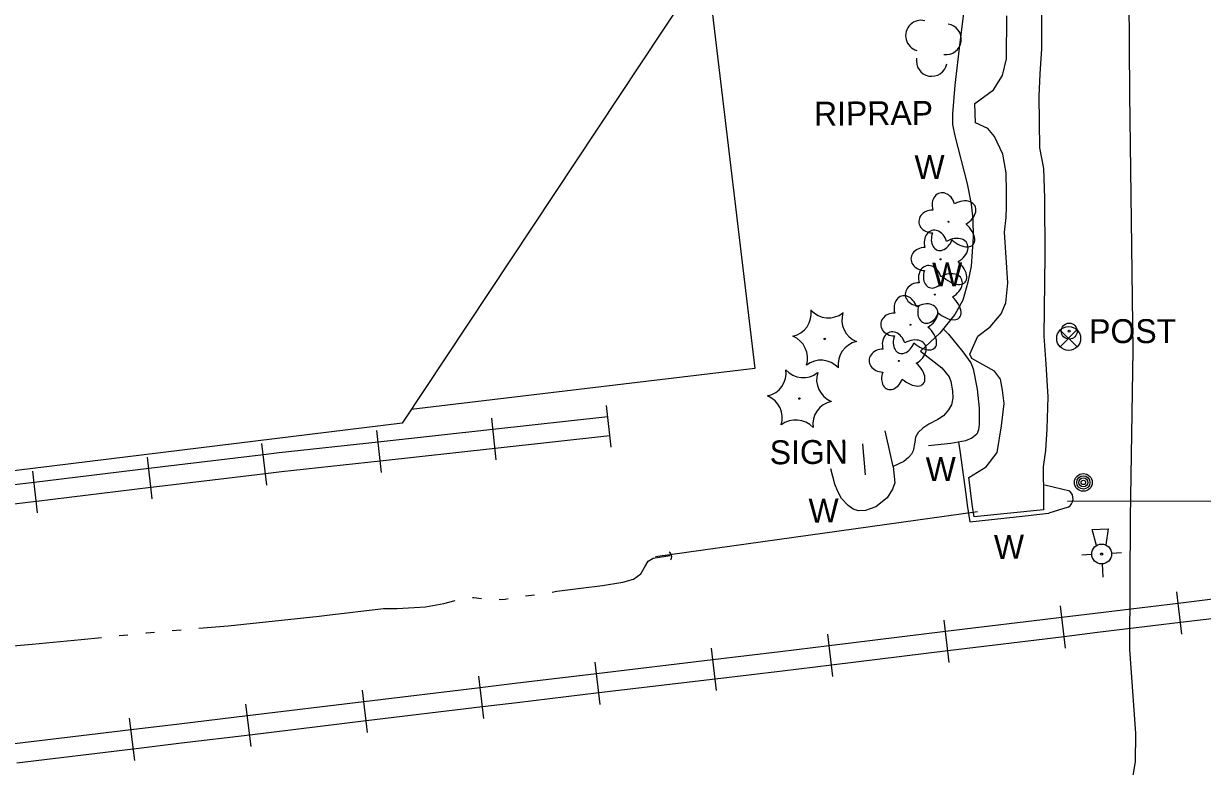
# Model space of a CAD drawing. Extents: x 589250 to 1188077, y 162953 to 363065.
# Drawn here: x 592485.5 to 592781.4, y 174759.1 to 174945.5 of the extents above; entities that cross this region are included whole.
import ezdxf

# ---------------------------------------------------------------- set-up
doc = ezdxf.new("R2010")
doc.units = 0
for name, color, linetype in [('E_BLD', 7, 'Continuous'), ('E_DRN', 7, 'Continuous'), ('E_DRN_Pipe', 7, 'Continuous'), ('E_DRN_RipRap', 7, 'Continuous'), ('E_DRN_RipRap_Text', 7, 'Continuous'), ('E_LAND_TreeLine_P', 7, 'Continuous'), ('E_LAND_Vegetation', 7, 'Continuous'), ('E_MAP_Limits', 7, 'Continuous'), ('E_MISCPROP', 7, 'Continuous'), ('E_RDWY', 7, 'Continuous'), ('E_RR_P', 7, 'Continuous'), ('E_RR_Utility', 7, 'Continuous'), ('E_SGN', 7, 'Continuous'), ('E_SGN_Text', 7, 'Continuous'), ('E_SIG', 7, 'Continuous'), ('E_STRUCT', 7, 'Continuous'), ('E_WAL', 7, 'Continuous'), ('E_WAL_Text', 7, 'Continuous'), ('E_WTR_FlowLine', 7, 'Continuous')]:
    doc.layers.add(name, color=color, linetype=linetype)

msp = doc.modelspace()

# ---------------------------------------------------------------- linework, layer by layer
at = {"layer": 'E_BLD'}
for p, q in [((592638.46, 175115.52), (592669, 174858.96)), ((592669, 174858.96), (592582.79, 174848.7))]:
    msp.add_line(p, q, dxfattribs=at)
at = {"layer": 'E_DRN'}
for centre, radius, start, end in [((592746.36, 174826.32), 2.56, 302.1619, 48.4222), ((592646.97, 174811.79), 1.21, 315.4865, 61.7467)]:
    msp.add_arc(centre, radius, start, end, dxfattribs=at)
at = {"layer": 'E_DRN_Pipe'}
for p, q in [((592747.53, 174825.68), (592807.85, 174825.81)), ((592724.94, 174823.05), (592644.14, 174811.7))]:
    msp.add_line(p, q, dxfattribs=at)
at = {"layer": 'E_DRN_RipRap'}
for p, q in [((592740.99, 174954.39), (592740.97, 174939.17)), ((592732.21, 174936.63), (592732.27, 174947.45)), ((592740.97, 174939.17), (592740.58, 174932.88)), ((592731.22, 174932.52), (592732.21, 174936.63)), ((592728.92, 174928.85), (592731.22, 174932.52)), ((592740.58, 174932.88), (592740.34, 174927.32)), ((592724.26, 174925.44), (592728.92, 174928.85)), ((592740.34, 174927.32), (592740.45, 174914.3)), ((592724.45, 174920.62), (592724.26, 174925.44)), ((592727.53, 174919.18), (592724.45, 174920.62)), ((592729.16, 174917.14), (592727.53, 174919.18)), ((592731.25, 174912.77), (592729.16, 174917.14)), ((592732.16, 174908.1), (592731.25, 174912.77)), ((592740.45, 174914.3), (592741.52, 174909.19)), ((592732.2, 174903.42), (592732.16, 174908.1)), ((592741.52, 174909.19), (592741.73, 174901.73)), ((592732.24, 174899.47), (592732.2, 174903.42)), ((592741.73, 174901.73), (592741.85, 174887.41)), ((592732.11, 174896.84), (592732.24, 174899.47)), ((592731.7, 174893.18), (592732.11, 174896.84)), ((592732.54, 174880.46), (592731.7, 174893.18)), ((592741.85, 174887.41), (592741.58, 174867.07)), ((592732, 174875.48), (592732.54, 174880.46)), ((592730.85, 174872.69), (592732, 174875.48)), ((592728.1, 174869.45), (592730.85, 174872.69)), ((592725.05, 174867.08), (592728.1, 174869.45)), ((592723.04, 174862.53), (592725.05, 174867.08)), ((592741.58, 174867.07), (592742.08, 174860.06)), ((592723.49, 174861.51), (592723.04, 174862.53)), ((592729.22, 174858.34), (592723.49, 174861.51)), ((592742.08, 174860.06), (592742.59, 174851.87)), ((592730.7, 174856.3), (592729.22, 174858.34)), ((592731.16, 174853.53), (592730.7, 174856.3)), ((592731.63, 174850.17), (592731.16, 174853.53)), ((592742.59, 174851.87), (592742.36, 174843.82)), ((592730.95, 174844.6), (592731.63, 174850.17)), ((592729.83, 174837.86), (592730.95, 174844.6)), ((592742.36, 174843.82), (592741.97, 174838.4)), ((592741.97, 174838.4), (592741.42, 174834.3)), ((592727.08, 174834.33), (592729.83, 174837.86)), ((592722.72, 174831.66), (592727.08, 174834.33)), ((592741.42, 174834.3), (592741.44, 174831.67)), ((592723.66, 174824.35), (592722.72, 174831.66)), ((592741.44, 174831.67), (592741.46, 174829.18)), ((592741.46, 174829.18), (592741.48, 174827.14)), ((592741.48, 174827.14), (592741.51, 174823.48)), ((592724.12, 174821.72), (592723.66, 174824.35)), ((592741.51, 174823.48), (592724.12, 174821.72))]:
    msp.add_line(p, q, dxfattribs=at)
at = {"layer": 'E_LAND_TreeLine_P'}
for centre, start, end in [((592710.73, 174942.48), 74.7778, 254.7778), ((592717, 174941.56), 262.1206, 82.1206), ((592713.43, 174936.13), 169.1765, 349.1765)]:
    msp.add_arc(centre, 3.85, start, end, dxfattribs=at)
at = {"layer": 'E_LAND_Vegetation'}
for centre, radius in [((592717.65, 174895.8), 0.128), ((592715.66, 174886.37), 0.128), ((592714.23, 174877.52), 0.128), ((592708.08, 174869.95), 0.128), ((592686.58, 174866.4), 0.167), ((592705.15, 174860.89), 0.128), ((592680.24, 174851.41), 0.167)]:
    msp.add_circle(centre, radius, dxfattribs=at)
for centre, radius, start, end in [((592677.32, 174872.84), 5.9, 282.2939, 8.0588), ((592687.5, 174877.57), 5.9, 222.2893, 308.0542), ((592696.78, 174871.19), 5.9, 162.2939, 248.0588), ((592676.37, 174861.6), 5.9, 342.2939, 68.0588), ((592695.83, 174859.96), 5.9, 102.2939, 188.0588), ((592685.63, 174855.15), 5.91, 42.3337, 128.0098), ((592670.98, 174857.85), 5.9, 282.2939, 8.0588), ((592681.17, 174862.59), 5.9, 222.2893, 308.0542), ((592690.44, 174856.2), 5.9, 162.2939, 248.0588), ((592670.04, 174846.61), 5.9, 342.2939, 68.0588), ((592689.5, 174844.97), 5.9, 102.2939, 188.0588), ((592679.29, 174840.16), 5.91, 42.3337, 128.0098)]:
    msp.add_arc(centre, radius, start, end, dxfattribs=at)
for centre, major_axis, ratio in [((592716.43, 174899.51), (0.99, -3.48), 0.782863), ((592720.59, 174897.74), (-3.67, -2.09), 0.691916), ((592713.66, 174895.86), (3.45, -0.05), 0.832022), ((592720.28, 174893.23), (-3.54, 3.17), 0.560249), ((592714.44, 174890.09), (0.99, -3.48), 0.782863), ((592716.07, 174892.11), (1.23, 3.41), 0.716896), ((592718.61, 174888.32), (-3.67, -2.09), 0.691916), ((592711.67, 174886.44), (3.45, -0.05), 0.832022), ((592718.29, 174883.81), (-3.54, 3.17), 0.560249), ((592713.01, 174881.23), (0.99, -3.48), 0.782863), ((592714.08, 174882.69), (1.23, 3.41), 0.716896), ((592717.18, 174879.47), (-3.67, -2.09), 0.691916), ((592710.24, 174877.59), (3.45, -0.05), 0.832022), ((592706.87, 174873.66), (0.99, -3.48), 0.782863), ((592716.86, 174874.95), (-3.54, 3.17), 0.560249), ((592712.65, 174873.84), (1.23, 3.41), 0.716896), ((592711.03, 174871.89), (-3.67, -2.09), 0.691916), ((592704.1, 174870.01), (3.45, -0.05), 0.832022), ((592703.93, 174864.61), (0.99, -3.48), 0.782863), ((592710.72, 174867.38), (-3.54, 3.17), 0.560249), ((592706.51, 174866.26), (1.23, 3.41), 0.716896), ((592708.1, 174862.84), (-3.67, -2.09), 0.691916), ((592701.17, 174860.96), (3.45, -0.05), 0.832022), ((592707.79, 174858.32), (-3.54, 3.17), 0.560249), ((592703.57, 174857.21), (1.23, 3.41), 0.716896)]:
    msp.add_ellipse(centre, major_axis=major_axis, ratio=ratio, start_param=1.570796, end_param=4.712389, dxfattribs=at)
at = {"layer": 'E_MAP_Limits'}
for p, q in [((592651.48, 174952.24), (592580.53, 174845.29)), ((592580.53, 174845.29), (592288.04, 174809.26))]:
    msp.add_line(p, q, dxfattribs=at)
at = {"layer": 'E_MISCPROP'}
for centre, radius in [((592747.95, 174868.35), 2), ((592747.95, 174868.35), 0.25), ((592751.49, 174830.39), 2.23), ((592751.49, 174830.39), 1.67), ((592751.49, 174830.39), 1.12), ((592751.49, 174830.39), 0.558)]:
    msp.add_circle(centre, radius, dxfattribs=at)
at = {"layer": 'E_RDWY'}
for p, q in [((592763.13, 174927.84), (592762.93, 174967.64)), ((592763.54, 174896.11), (592763.13, 174927.84)), ((592763.96, 174863.54), (592763.54, 174896.11)), ((592763.33, 174821.47), (592763.96, 174863.54)), ((592763.18, 174788.6), (592763.33, 174821.47)), ((592764.63, 174767.37), (592763.18, 174788.6)), ((592764.55, 174760.29), (592764.63, 174767.37)), ((592763.61, 174754.33), (592764.55, 174760.29))]:
    msp.add_line(p, q, dxfattribs=at)
at = {"layer": 'E_RR_P'}
for p, q in [((592632.96, 174839.22), (592631.82, 174849.68)), ((592604.14, 174836.07), (592603, 174846.53)), ((592632.13, 174846.83), (592603.32, 174843.68)), ((592575.33, 174832.91), (592574.19, 174843.38)), ((592603.31, 174843.68), (592574.5, 174840.53)), ((592632.65, 174842.07), (592603.84, 174838.92)), ((592546.6, 174829.73), (592545.34, 174840.17)), ((592574.5, 174840.53), (592549.68, 174837.81)), ((592603.83, 174838.92), (592575.02, 174835.76)), ((592517.82, 174826.25), (592516.57, 174836.69)), ((592545.69, 174837.33), (592516.91, 174833.85)), ((592549.68, 174837.81), (592545.69, 174837.33)), ((592575.02, 174835.76), (592550.23, 174833.05)), ((592489.04, 174822.77), (592487.79, 174833.22)), ((592516.91, 174833.85), (592488.13, 174830.37)), ((592546.26, 174832.57), (592517.49, 174829.09)), ((592550.23, 174833.05), (592546.26, 174832.57)), ((592488.13, 174830.37), (592466.38, 174827.74)), ((592517.48, 174829.09), (592488.71, 174825.61)), ((592488.7, 174825.61), (592466.96, 174822.99)), ((592776.22, 174792.33), (592774.94, 174802.94)), ((592804.49, 174803.59), (592775.29, 174800.05)), ((592775.29, 174800.05), (592754.46, 174797.52)), ((592747.02, 174788.79), (592745.74, 174799.39)), ((592754.46, 174797.52), (592746.09, 174796.5)), ((592805.07, 174798.76), (592775.88, 174795.22)), ((592717.83, 174785.24), (592716.54, 174795.84)), ((592746.09, 174796.5), (592716.9, 174792.96)), ((592775.87, 174795.22), (592755.05, 174792.7)), ((592688.63, 174781.69), (592687.35, 174792.3)), ((592716.89, 174792.96), (592687.7, 174789.41)), ((592746.68, 174791.68), (592717.48, 174788.13)), ((592755.05, 174792.7), (592746.68, 174791.68)), ((592659.41, 174778.17), (592658.15, 174788.78)), ((592687.69, 174789.41), (592675.36, 174787.91)), ((592717.48, 174788.13), (592688.28, 174784.58)), ((592630.21, 174774.68), (592628.94, 174785.28)), ((592658.49, 174785.89), (592629.29, 174782.39)), ((592675.36, 174787.91), (592658.49, 174785.89)), ((592629.29, 174782.39), (592608.77, 174779.94)), ((592675.95, 174783.08), (592659.07, 174781.06)), ((592688.28, 174784.58), (592675.95, 174783.08)), ((592601.01, 174771.17), (592599.74, 174781.78)), ((592608.77, 174779.94), (592600.09, 174778.89)), ((592659.07, 174781.06), (592629.87, 174777.57)), ((592571.81, 174767.65), (592570.53, 174778.25)), ((592600.08, 174778.89), (592570.88, 174775.36)), ((592629.86, 174777.57), (592609.35, 174775.11)), ((592542.61, 174764.12), (592541.33, 174774.73)), ((592570.88, 174775.36), (592541.68, 174771.84)), ((592600.66, 174774.06), (592571.47, 174770.54)), ((592609.35, 174775.11), (592600.67, 174774.06)), ((592513.4, 174760.61), (592512.13, 174771.21)), ((592541.68, 174771.84), (592524.56, 174769.77)), ((592571.46, 174770.54), (592542.27, 174767.01)), ((592512.48, 174768.32), (592483.27, 174764.83)), ((592524.56, 174769.77), (592512.48, 174768.32)), ((592525.14, 174764.95), (592513.06, 174763.5)), ((592542.26, 174767.01), (592525.14, 174764.95)), ((592513.05, 174763.5), (592483.85, 174760))]:
    msp.add_line(p, q, dxfattribs=at)
at = {"layer": 'E_RR_Utility'}
for p, q in [((592753.59, 174812.29), (592751.09, 174812.15)), ((592761.07, 174812.7), (592758.58, 174812.56)), ((592756.22, 174809.93), (592756.4, 174806.63))]:
    msp.add_line(p, q, dxfattribs=at)
msp.add_lwpolyline([(592754.81, 174814.58), (592753.74, 174818.56), (592757.74, 174818.78), (592757.11, 174814.7)], dxfattribs=at)
for radius in [2.5, 0.25]:
    msp.add_circle((592756.08, 174812.43), radius, dxfattribs=at)
at = {"layer": 'E_SGN'}
msp.add_line((592696.05, 174840.05), (592696.76, 174832.26), dxfattribs=at)
at = {"layer": 'E_SIG'}
for points in [[(592749.86, 174868.65), (592745.67, 174864.42)], [(592745.67, 174868.61), (592749.9, 174864.38)]]:
    msp.add_lwpolyline(points, dxfattribs=at)
msp.add_circle((592747.81, 174866.53), 3, dxfattribs=at)
at = {"layer": 'E_STRUCT'}
for p, q in [((592748.06, 174828.24), (592741.86, 174829.67)), ((592747.72, 174824.15), (592742.79, 174822.65))]:
    msp.add_line(p, q, dxfattribs=at)
at = {"layer": 'E_WAL'}
for p, q in [((592722.51, 174957.1), (592720.51, 174940.74)), ((592720.51, 174940.74), (592719.21, 174930.05)), ((592719.21, 174930.05), (592718.63, 174922.89)), ((592718.63, 174922.89), (592718.65, 174920.22)), ((592718.65, 174920.22), (592719.21, 174917.34)), ((592719.21, 174917.34), (592722.31, 174905.3)), ((592722.31, 174905.3), (592723.31, 174900.18)), ((592723.31, 174900.18), (592723.77, 174896.47)), ((592723.77, 174896.47), (592723.81, 174891.98)), ((592723.81, 174891.98), (592723.34, 174884.61)), ((592723.34, 174884.61), (592722.51, 174880.65)), ((592722.51, 174880.65), (592721.27, 174876.15)), ((592721.27, 174876.15), (592719.27, 174872.51)), ((592719.27, 174872.51), (592715.47, 174867.88)), ((592716.34, 174868.94), (592717.61, 174867.58)), ((592715.47, 174867.88), (592710.59, 174863.35)), ((592717.61, 174867.58), (592721.27, 174863.12)), ((592710.59, 174863.35), (592715.97, 174859.13)), ((592721.27, 174863.12), (592723.22, 174860.36)), ((592715.97, 174859.13), (592717.8, 174856.9)), ((592723.22, 174860.36), (592723.87, 174858.87)), ((592717.8, 174856.9), (592718.24, 174855.73)), ((592723.87, 174858.87), (592724.88, 174853.75)), ((592718.24, 174855.73), (592718.69, 174853.38)), ((592718.69, 174853.38), (592718.7, 174851.57)), ((592724.88, 174853.75), (592725.35, 174849.06)), ((592718.7, 174851.57), (592718.4, 174849.85)), ((592717.66, 174848.57), (592716.39, 174847.06)), ((592718.4, 174849.85), (592717.66, 174848.57)), ((592725.35, 174849.06), (592725.38, 174844.89)), ((592712.67, 174845), (592711.18, 174844.02)), ((592715.01, 174846.19), (592712.67, 174845)), ((592716.39, 174847.06), (592715.01, 174846.19)), ((592725.38, 174844.89), (592725.18, 174843.61)), ((592702.79, 174838.93), (592701.79, 174843.3)), ((592709.39, 174841.77), (592709.18, 174840.48)), ((592710.02, 174842.95), (592709.39, 174841.77)), ((592711.18, 174844.02), (592710.02, 174842.95)), ((592723.49, 174841.46), (592721.89, 174840.8)), ((592724.76, 174842.54), (592723.49, 174841.46)), ((592725.18, 174843.61), (592724.76, 174842.54)), ((592703.79, 174834.35), (592702.79, 174838.93)), ((592709.18, 174840.48), (592708.77, 174838.34)), ((592718.27, 174840.13), (592712.61, 174839.55)), ((592721.89, 174840.8), (592718.27, 174840.13)), ((592720.15, 174840.48), (592720.52, 174838.44)), ((592720.52, 174838.44), (592722, 174827.45)), ((592706.45, 174835.65), (592703.79, 174834.35)), ((592707.61, 174836.62), (592706.45, 174835.65)), ((592708.35, 174837.48), (592707.61, 174836.62)), ((592708.77, 174838.34), (592708.35, 174837.48)), ((592689.09, 174829.95), (592688.09, 174833.79)), ((592703.79, 174834.35), (592704.14, 174830.29)), ((592689.85, 174828.14), (592689.09, 174829.95)), ((592704.14, 174830.29), (592703.62, 174828.69)), ((592690.82, 174826.33), (592689.85, 174828.14)), ((592702.25, 174826.54), (592699.39, 174824.27)), ((592703.62, 174828.69), (592702.25, 174826.54)), ((592722, 174827.45), (592722.35, 174824.68)), ((592692.44, 174824.64), (592690.82, 174826.33)), ((592693.73, 174823.69), (592692.44, 174824.64)), ((592695.02, 174823.27), (592693.73, 174823.69)), ((592699.39, 174824.27), (592696.83, 174823.39)), ((592722.35, 174824.68), (592723.02, 174820.52)), ((592696.83, 174823.39), (592695.02, 174823.27)), ((592723.02, 174820.52), (592734.66, 174821.79)), ((592734.66, 174821.79), (592742.79, 174822.65))]:
    msp.add_line(p, q, dxfattribs=at)
at = {"layer": 'E_WTR_FlowLine'}
for p, q in [((592643.53, 174811.37), (592647.75, 174812.03)), ((592640.46, 174807.49), (592641.44, 174809.24)), ((592641.44, 174809.24), (592642.29, 174810.62)), ((592642.29, 174810.62), (592643.53, 174811.37)), ((592635.88, 174805.34), (592638.6, 174806.11)), ((592638.6, 174806.11), (592640.46, 174807.49)), ((592618.14, 174802.9), (592619.37, 174803.09)), ((592619.37, 174803.09), (592625.33, 174803.88)), ((592625.33, 174803.88), (592630.79, 174804.55)), ((592630.79, 174804.55), (592635.88, 174805.34)), ((592586.36, 174799.21), (592590.95, 174799.99)), ((592590.95, 174799.99), (592593.85, 174800.74)), ((592598.21, 174801.54), (592598.52, 174801.55)), ((592598.52, 174801.55), (592600.43, 174801.27)), ((592604.87, 174801.05), (592606.35, 174801.11)), ((592606.35, 174801.11), (592607.1, 174801.23)), ((592611.51, 174801.9), (592613.72, 174802.23)), ((592559.67, 174796.87), (592561.73, 174797.11)), ((592561.73, 174797.11), (592575.81, 174798.74)), ((592575.81, 174798.74), (592579.29, 174798.77)), ((592579.29, 174798.77), (592586.36, 174799.21)), ((592529.51, 174793.8), (592536.84, 174794.44)), ((592536.84, 174794.44), (592559.67, 174796.87)), ((592499.98, 174791.02), (592505.04, 174791.52)), ((592509.49, 174791.97), (592511.71, 174792.19)), ((592516.15, 174792.63), (592516.35, 174792.65)), ((592516.35, 174792.65), (592518.38, 174792.83)), ((592522.83, 174793.21), (592525.06, 174793.41)), ((592472.78, 174788.55), (592487.69, 174789.8)), ((592487.69, 174789.8), (592499.98, 174791.02))]:
    msp.add_line(p, q, dxfattribs=at)

# ---------------------------------------------------------------- texts
at = {"layer": 'E_DRN_RipRap_Text'}
msp.add_text('RIPRAP', height=6, rotation=0.4865, dxfattribs=at).set_placement((592683.91, 174919.88))
at = {"layer": 'E_MISCPROP'}
msp.add_text('POST', height=6, dxfattribs=at).set_placement((592752.95, 174865.35))
at = {"layer": 'E_SGN_Text'}
msp.add_text('SIGN', height=6, rotation=0.4865, dxfattribs=at).set_placement((592672.8, 174834.93))
at = {"layer": 'E_WAL_Text'}
for p in [(592709.15, 174906.48), (592713.58, 174879.55), (592711.96, 174830.72), (592682.56, 174820.3), (592729.08, 174811.2)]:
    msp.add_text('W', height=6, rotation=0.4865, dxfattribs=at).set_placement(p)

doc.saveas('drawing.dxf')
